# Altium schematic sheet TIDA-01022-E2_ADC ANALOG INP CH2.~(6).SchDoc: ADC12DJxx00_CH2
size 431 x 279 mm; Date: Not shown in title block; ApprovedBy: Not shown in title block; CheckedBy: Not shown in title block; Author: Not shown in title block; CompanyName: Not shown in title block; DrawnBy: Avinash N; Engineer: Not shown in title block; Organization: Not shown in title block; Address1: Not shown in title block; Address2: Not shown in title block; Address3: Not shown in title block; Address4: Not shown in title block; DocumentNumber: 1; Revision: Use project parameter SCH_Rev; SheetNumber: 3; SheetTotal: 26; PageSetup: Record=PageOptions¦CenterHorizontal=True¦CenterVertical=True¦PrintScale=1.00¦XCorrection=1.00¦YCorrection=1.00¦PrintKind=0¦BorderSize=5000000¦LeftOffset=0¦BottomOffset=0¦Orientation=2¦PaperLength=1000¦PaperWidth=1000¦Scale=100¦PaperSource=15¦PrintQuality=600¦MediaType=1¦DitherType=10¦PaperKind=Letter¦PrintScaleMode=1
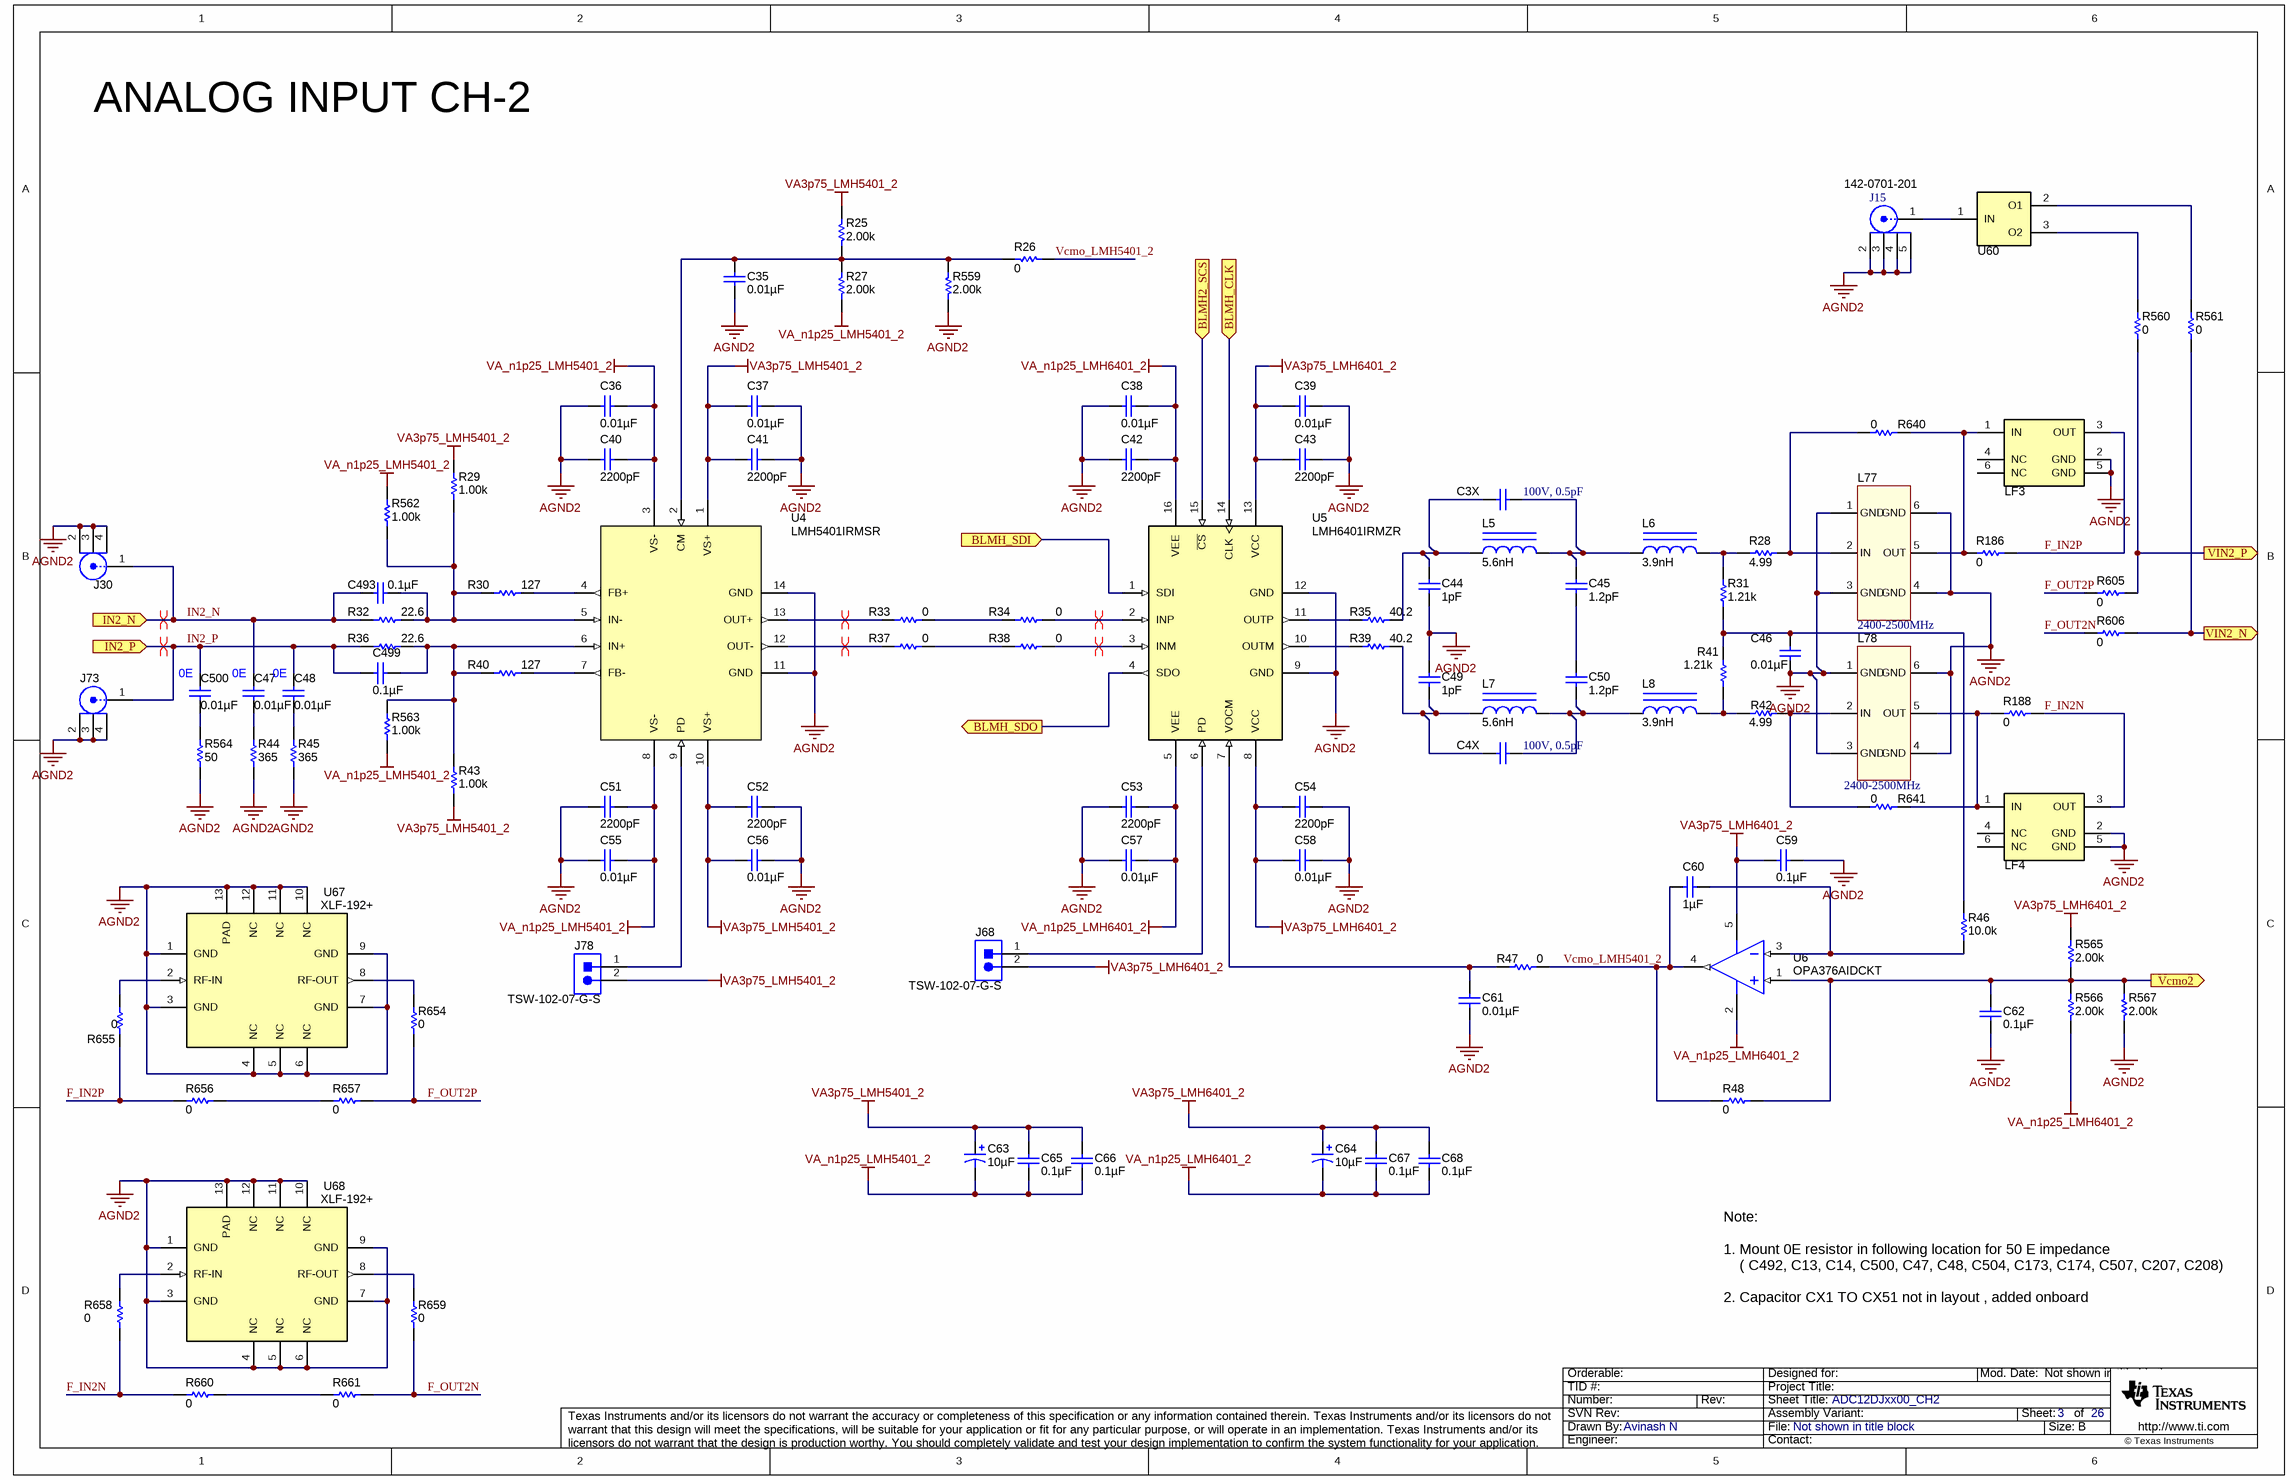
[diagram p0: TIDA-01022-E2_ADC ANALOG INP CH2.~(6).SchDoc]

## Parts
C3X  100V, 0.5pF  [0603_1.6x0.8x0.8mm_Reflow Soldering]
C4X  100V, 0.5pF  [0603_1.6x0.8x0.8mm_Reflow Soldering]
C35  ValueDisplayed: 0.01µF  [0402]  (hidden comment: GRM155R71E103KA01D)
C36  ValueDisplayed: 0.01µF  [0306]  (hidden comment: LLL185R71E103MA01L)
C37  ValueDisplayed: 0.01µF  [0306]  (hidden comment: LLL185R71E103MA01L)
C38  ValueDisplayed: 0.01µF  [0306]  (hidden comment: LLL185R71E103MA01L)
C39  ValueDisplayed: 0.01µF  [0306]  (hidden comment: LLL185R71E103MA01L)
C40  ValueDisplayed: 2200pF  [0306]  (hidden comment: LLL185R71H222MA01L)
C41  ValueDisplayed: 2200pF  [0306]  (hidden comment: LLL185R71H222MA01L)
C42  ValueDisplayed: 2200pF  [0306]  (hidden comment: LLL185R71H222MA01L)
C43  ValueDisplayed: 2200pF  [0306]  (hidden comment: LLL185R71H222MA01L)
C44  ValueDisplayed: 1pF  [0402]  (hidden comment: GRM1555C1H1R0CA01D)
C45  ValueDisplayed: 1.2pF  [0402]  (hidden comment: GRM1555C1H1R2BA01D)
C46  ValueDisplayed: 0.01µF  [0402]  (hidden comment: GRM155R71E103KA01D)
C47  ValueDisplayed: 0.01µF  [0402]  (hidden comment: GRM155R71E103KA01D)
C48  ValueDisplayed: 0.01µF  [0402]  (hidden comment: GRM155R71E103KA01D)
C49  ValueDisplayed: 1pF  [0402]  (hidden comment: GRM1555C1H1R0CA01D)
C50  ValueDisplayed: 1.2pF  [0402]  (hidden comment: GRM1555C1H1R2BA01D)
C51  ValueDisplayed: 2200pF  [0306]  (hidden comment: LLL185R71H222MA01L)
C52  ValueDisplayed: 2200pF  [0306]  (hidden comment: LLL185R71H222MA01L)
C53  ValueDisplayed: 2200pF  [0306]  (hidden comment: LLL185R71H222MA01L)
C54  ValueDisplayed: 2200pF  [0306]  (hidden comment: LLL185R71H222MA01L)
C55  ValueDisplayed: 0.01µF  [0306]  (hidden comment: LLL185R71E103MA01L)
C56  ValueDisplayed: 0.01µF  [0306]  (hidden comment: LLL185R71E103MA01L)
C57  ValueDisplayed: 0.01µF  [0306]  (hidden comment: LLL185R71E103MA01L)
C58  ValueDisplayed: 0.01µF  [0306]  (hidden comment: LLL185R71E103MA01L)
C59  ValueDisplayed: 0.1µF  [0402]  (hidden comment: C1005X5R1A104K050BA)
C60  ValueDisplayed: 1µF  [0603]  (hidden comment: C1608X5R1A105K080AC)
C61  ValueDisplayed: 0.01µF  [0402]  (hidden comment: GRM155R71E103KA01D)
C62  ValueDisplayed: 0.1µF  [0402]  (hidden comment: C1005X5R1A104K050BA)
C63  ValueDisplayed: 10µF  [3216-18]  (hidden comment: TPSA106K010R0900)
C64  ValueDisplayed: 10µF  [3216-18]  (hidden comment: TPSA106K010R0900)
C65  ValueDisplayed: 0.1µF  [0402]  (hidden comment: C1005X5R1A104K050BA)
C66  ValueDisplayed: 0.1µF  [0402]  (hidden comment: C1005X5R1A104K050BA)
C67  ValueDisplayed: 0.1µF  [0402]  (hidden comment: C1005X5R1A104K050BA)
C68  ValueDisplayed: 0.1µF  [0402]  (hidden comment: C1005X5R1A104K050BA)
C493  ValueDisplayed: 0.1µF  [0402]  (hidden comment: GRM155R71C104JA88D)
C499  ValueDisplayed: 0.1µF  [0402]  (hidden comment: GRM155R71C104JA88D)
C500  ValueDisplayed: 0.01µF  [0402]  (hidden comment: GRM155R71E103KA01D)
J15  142-0701-201  [Johnson_142-0701-20x]
J30  142-0771-831  [Johnson_142-0771-831]  (value not drawn)
J68  TSW-102-07-G-S  [TSW-102-07-G-S]
J73  142-0771-831  [Johnson_142-0771-831]  (value not drawn)
J78  TSW-102-07-G-S  [TSW-102-07-G-S]
L5  ValueDisplayed: 5.6nH  [LQW18A]  (hidden comment: LQW18AN5N6D10D)
L6  ValueDisplayed: 3.9nH  [0603HC]  (hidden comment: 0603HC-3N9XJLU)
L7  ValueDisplayed: 5.6nH  [LQW18A]  (hidden comment: LQW18AN5N6D10D)
L8  ValueDisplayed: 3.9nH  [0603HC]  (hidden comment: 0603HC-3N9XJLU)
L77  value 2400-2500MHz  [WE-LPF_0603]  (hidden comment: WE-LPF, 748112024)
L78  value 2400-2500MHz  [WE-LPF_0603]  (hidden comment: WE-LPF, 748112024)
LF3  LFL182G45TC3B746  [FIL_LFL18_TC1]  (value not drawn)
LF4  LFL182G45TC3B746  [FIL_LFL18_TC1]  (value not drawn)
R25  ValueDisplayed: 2.00k  [0402]  (hidden comment: CRCW04022K00FKED)
R26  ValueDisplayed: 0  [0402]  (hidden comment: CRCW04020000Z0ED)
R27  ValueDisplayed: 2.00k  [0402]  (hidden comment: CRCW04022K00FKED)
R28  ValueDisplayed: 4.99  [0402]  (hidden comment: CRCW04024R99FKED)
R29  ValueDisplayed: 1.00k  [0402]  (hidden comment: ERJ-2RKF1001X)
R30  ValueDisplayed: 127  [0402]  (hidden comment: CRCW0402127RFKED)
R31  ValueDisplayed: 1.21k  [0402]  (hidden comment: CRCW04021K21FKED)
R32  ValueDisplayed: 22.6  [0402]  (hidden comment: CRCW040222R6FKED)
R33  ValueDisplayed: 0  [0402]  (hidden comment: CRCW04020000Z0ED)
R34  ValueDisplayed: 0  [0402]  (hidden comment: CRCW04020000Z0ED)
R35  ValueDisplayed: 40.2  [0402]  (hidden comment: CRCW040240R2FKED)
R36  ValueDisplayed: 22.6  [0402]  (hidden comment: CRCW040222R6FKED)
R37  ValueDisplayed: 0  [0402]  (hidden comment: CRCW04020000Z0ED)
R38  ValueDisplayed: 0  [0402]  (hidden comment: CRCW04020000Z0ED)
R39  ValueDisplayed: 40.2  [0402]  (hidden comment: CRCW040240R2FKED)
R40  ValueDisplayed: 127  [0402]  (hidden comment: CRCW0402127RFKED)
R41  ValueDisplayed: 1.21k  [0402]  (hidden comment: CRCW04021K21FKED)
R42  ValueDisplayed: 4.99  [0402]  (hidden comment: CRCW04024R99FKED)
R43  ValueDisplayed: 1.00k  [0402]  (hidden comment: ERJ-2RKF1001X)
R44  ValueDisplayed: 365  [0402]  (hidden comment: CRCW0402365RFKED)
R45  ValueDisplayed: 365  [0402]  (hidden comment: CRCW0402365RFKED)
R46  ValueDisplayed: 10.0k  [0402]  (hidden comment: CRCW040210K0FKED)
R47  ValueDisplayed: 0  [0402]  (hidden comment: CRCW04020000Z0ED)
R48  ValueDisplayed: 0  [0402]  (hidden comment: CRCW04020000Z0ED)
R186  ValueDisplayed: 0  [0402_FILTER]  (hidden comment: CRCW04020000Z0ED)
R188  ValueDisplayed: 0  [0402_FILTER]  (hidden comment: CRCW04020000Z0ED)
R559  ValueDisplayed: 2.00k  [0402]  (hidden comment: CRCW04022K00FKED)
R560  ValueDisplayed: 0  [0201_adc]  (hidden comment: CRCW02010000Z0ED)
R561  ValueDisplayed: 0  [0201_adc]  (hidden comment: CRCW02010000Z0ED)
R562  ValueDisplayed: 1.00k  [0402]  (hidden comment: ERJ-2RKF1001X)
R563  ValueDisplayed: 1.00k  [0402]  (hidden comment: ERJ-2RKF1001X)
R564  ValueDisplayed: 50  [0402]  (hidden comment: FC0402E50R0BTBST1)
R565  ValueDisplayed: 2.00k  [0402]  (hidden comment: CRCW04022K00FKED)
R566  ValueDisplayed: 2.00k  [0402]  (hidden comment: CRCW04022K00FKED)
R567  ValueDisplayed: 2.00k  [0402]  (hidden comment: CRCW04022K00FKED)
R605  ValueDisplayed: 0  [0201_adc]  (hidden comment: CRCW02010000Z0ED)
R606  ValueDisplayed: 0  [0201_adc]  (hidden comment: CRCW02010000Z0ED)
R640  ValueDisplayed: 0  [0402_FILTER]  (hidden comment: CRCW04020000Z0ED)
R641  ValueDisplayed: 0  [0402_FILTER]  (hidden comment: CRCW04020000Z0ED)
R654  ValueDisplayed: 0  [0201_adc]  (hidden comment: CRCW02010000Z0ED)
R655  ValueDisplayed: 0  [0201_adc]  (hidden comment: CRCW02010000Z0ED)
R656  ValueDisplayed: 0  [0201_adc]  (hidden comment: CRCW02010000Z0ED)
R657  ValueDisplayed: 0  [0201_adc]  (hidden comment: CRCW02010000Z0ED)
R658  ValueDisplayed: 0  [0201_adc]  (hidden comment: CRCW02010000Z0ED)
R659  ValueDisplayed: 0  [0201_adc]  (hidden comment: CRCW02010000Z0ED)
R660  ValueDisplayed: 0  [0201_adc]  (hidden comment: CRCW02010000Z0ED)
R661  ValueDisplayed: 0  [0201_adc]  (hidden comment: CRCW02010000Z0ED)
U4  LMH5401IRMSR  [RMS0014A]
U5  LMH6401IRMZR  [RMZ0016A]
U6  OPA376AIDCKT  [DCK0005A_N]
U60  BAL-0006SMG  [Marki_BAL-0006SMG]  (value not drawn)
U67  XLF-192+  [DQ1225]
U68  XLF-192+  [DQ1225]

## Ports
BLMH2_SCS (in), BLMH_CLK (in), BLMH_SDI (in), BLMH_SDO (out), IN2_N (in), IN2_P (in), Vcmo2 (out), VIN2_N (out), VIN2_P (out)

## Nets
AGND2: C35.2 C36.1 C37.1 C38.1 C39.1 C40.2 C41.2 C42.2 C43.2 C44.2 C46.2 C49.2 C51.2 C52.2 C53.2 C54.2 C55.1 C56.1 C57.1 C58.1 C59.1 C61.2 C62.2 J15.2 J15.3 J15.4 J15.5 J30.2 J30.3 J30.4 J73.2 J73.3 J73.4 L77.1(GND) L77.3(GND) L77.4(GND) L77.6(GND) L78.1(GND) L78.3(GND) L78.4(GND) L78.6(GND) LF3.2(GND) LF3.5(GND) LF4.2(GND) LF4.5(GND) R44.1 R45.1 R559.1 R564.1 R567.1 U4.11(GND) U4.14(GND) U5.9(GND) U5.12(GND) U67.1(GND) U67.3(GND) U67.4(NC) U67.5(NC) U67.6(NC) U67.7(GND) U67.9(GND) U67.10(NC) U67.11(NC) U67.12(NC) U67.13(PAD) U68.1(GND) U68.3(GND) U68.4(NC) U68.5(NC) U68.6(NC) U68.7(GND) U68.9(GND) U68.10(NC) U68.11(NC) U68.12(NC) U68.13(PAD)
VA3p75_LMH5401_2: C37.2 C41.1 C52.1 C56.2 C63.1(+) C65.1 C66.1 J78.2 R25.2 R29.2 R43.1 U4.1(VS+) U4.10(VS+)
VA3p75_LMH6401_2: C39.2 C43.1 C54.1 C58.2 C59.2 C64.1(+) C67.1 C68.1 J68.2 R565.2 U5.8(VCC) U5.13(VCC) U6.5(V+)
VA_n1p25_LMH5401_2: C36.2 C40.1 C51.1 C55.2 C63.2(-) C65.2 C66.2 R27.1 R562.2 R563.2 U4.3(VS-) U4.8(VS-)
VA_n1p25_LMH6401_2: C38.2 C42.1 C53.1 C57.2 C64.2(-) C67.2 C68.2 R566.1 U5.5(VEE) U5.16(VEE) U6.2(V-)
BLMH2_SCS: U5.15(~{CS}) ; port BLMH2_SCS
BLMH_CLK: U5.14(CLK) ; port BLMH_CLK
BLMH_SDI: U5.1(SDI) ; port BLMH_SDI
BLMH_SDO: U5.4(SDO) ; port BLMH_SDO
F_IN2N: LF4.3(OUT) R188.2 R658.1 R660.1
F_IN2P: LF3.3(OUT) R186.2 R655.1 R656.1
F_OUT2N: R606.1 R659.1 R661.2
F_OUT2P: R605.1 R654.1 R657.2
IN2_N: C47.1 C493.2 J30.1 R32.1 ; port IN2_N
IN2_P: C48.1 C499.1 C500.1 J73.1 R36.1 ; port IN2_P
Vcmo2: C62.1 R48.1 R565.1 R566.2 R567.2 U6.1(IN+) ; port Vcmo2
Vcmo_LMH5401_2: C60.1 R26.2 R47.1 R48.2 U6.4(OUT)
VIN2_N: R561.2 R606.2 ; port VIN2_N
VIN2_P: R560.2 R605.2 ; port VIN2_P
NetC3X_1: C3X.1 C44.1 L5.1 R35.1
NetC3X_2: C3X.2 C45.1 L5.2 L6.1
NetC4X_1: C4X.1 C49.1 L7.1 R39.1
NetC4X_2: C4X.2 C50.1 L7.2 L8.1
NetC35_1: C35.1 R25.1 R26.1 R27.2 R559.2 U4.2(CM)
NetC45_2: C45.2 C50.2
NetC46_1: C46.1 R31.1 R41.1 R46.2
NetC47_2: C47.2 R44.2
NetC48_2: C48.2 R45.2
NetC60_2: C60.2 R46.1 U6.3(IN-)
NetC61_1: C61.1 R47.2 U5.7(VOCM)
NetC493_1: C493.1 R29.1 R30.1 R32.2 R562.1 U4.5(IN-)
NetC499_2: C499.2 R36.2 R40.1 R43.2 R563.1 U4.6(IN+)
NetC500_2: C500.2 R564.2
NetJ15_1: J15.1 U60.1(IN)
NetJ68_1: J68.1 U5.6(PD)
NetJ78_1: J78.1 U4.9(PD)
NetL6_2: L6.2 R28.1 R31.2
NetL8_2: L8.2 R41.2 R42.1
NetL77_2: L77.2(IN) R28.2 R640.1
NetL77_5: L77.5(OUT) LF3.1(IN) R186.1 R640.2
NetL78_2: L78.2(IN) R42.2 R641.1
NetL78_5: L78.5(OUT) LF4.1(IN) R188.1 R641.2
NetR30_2: R30.2 U4.4(FB+)
NetR33_1: R33.1 U4.13(OUT+)
NetR33_2: R33.2 R34.2
NetR34_1: R34.1 U5.2(INP)
NetR35_2: R35.2 U5.11(OUTP)
NetR37_1: R37.1 U4.12(OUT-)
NetR37_2: R37.2 R38.2
NetR38_1: R38.1 U5.3(INM)
NetR39_2: R39.2 U5.10(OUTM)
NetR40_2: R40.2 U4.7(FB-)
NetR560_1: R560.1 U60.3(O2)
NetR561_1: R561.1 U60.2(O1)
NetR654_2: R654.2 U67.8(RF-OUT)
NetR655_2: R655.2 U67.2(RF-IN)
NetR656_2: R656.2 R657.1
NetR658_2: R658.2 U68.2(RF-IN)
NetR659_2: R659.2 U68.8(RF-OUT)
NetR660_2: R660.2 R661.1

Not connected (* = marked no-connect by the designer): LF3 4(NC) 6(NC); LF4 4(NC) 6(NC)

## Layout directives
differential pair: IN2_N, IN2_P, NetR33_1, NetR34_1, NetR37_1, NetR38_1

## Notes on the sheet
- ANALOG INPUT CH-2
- (near C500) 0E
- (near C47) 0E
- (near C48) 0E
- Note:
  1. Mount 0E resistor in following location for 50 E impedance
  ( C492, C13, C14, C500, C47, C48, C504, C173, C174, C507, C207, C208)
  2. Capacitor CX1 TO CX51 not in layout , added onboard

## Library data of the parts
C3X C4X = 885012006086: WCAP-CSGP Ceramic Capacitors, 0603, NP0, 100V, 0.5pF; Rated Voltage: 100V DC
C35 C46-C48 C61 C500 = GRM155R71E103KA01D: CAP, CERM, 0.01 µF, 25 V, +/- 10%, X7R, 0402; Manufacturer: MuRata; Polarized: N; CompType: Capacitor; Value: 0.01uF; U/M: EA; Cap_F: 0.00000001; Tolerance_%: 10; Value1: Unknown; VDC_V: 25; Value2: 25V; TaMin_C: -55; TaMax_C: 125; SizeArea_mm2: 0.5; SizeAreaWB_mm2: 3; SizeX_mm: 1; SizeZ_mm: 0.6; AEC Category: Q200
C36-C39 C55-C58 = LLL185R71E103MA01L: CAP, CERM, 0.01 µF, 25 V, +/- 20%, X7R, 0306; Manufacturer: MuRata; Polarized: N; CompType: Capacitor; Value: 0.01uF; U/M: EA; Cap_F: 0.00000001; Tolerance_%: 20; Value1: Unknown; VDC_V: 25; Value2: 25V; TaMin_C: -55; TaMax_C: 125; SizeArea_mm2: 1.28; SizeAreaWB_mm2: 4.68; SizeX_mm: 0.8; SizeY_mm: 1.6; SizeZ_mm: 0.6; AEC Category: Q200
C40-C43 C51-C54 = LLL185R71H222MA01L: CAP, CERM, 2200 pF, 50 V, +/- 20%, X7R, 0306; Manufacturer: MuRata; Polarized: N; CompType: Capacitor; Value: 2200pF; U/M: EA; Cap_F: 0.0000000022; Tolerance_%: 20; Value1: Unknown; VDC_V: 50; Value2: 50V; TaMin_C: -55; TaMax_C: 125; SizeArea_mm2: 1.28; SizeAreaWB_mm2: 4.68; SizeX_mm: 0.8; SizeY_mm: 1.6; SizeZ_mm: 0.6; AEC Category: Q200
C44 C49 = GRM1555C1H1R0CA01D: CAP, CERM, 1 pF, 50 V, +/- 5%, C0G/NP0, 0402; Manufacturer: MuRata; Polarized: N; CompType: Capacitor; Value: 1pF; U/M: EA; Cap_F: 0.000000000001; Tolerance_%: 5; Value1: Unknown; VDC_V: 50; Value2: 50V; TaMin_C: -55; TaMax_C: 125; SizeArea_mm2: 0.5; SizeAreaWB_mm2: 3; SizeX_mm: 1; SizeZ_mm: 0.6; AEC Category: Q200
C45 C50 = GRM1555C1H1R2BA01D: CAP, CERM, 1.2 pF, 50 V, +/- 8.3%, C0G/NP0, 0402; Manufacturer: MuRata; Polarized: N; CompType: Capacitor; Value: 1.2pF; U/M: EA; Cap_F: 0.0000000000012; Tolerance_%: 8.3; Value1: Unknown; VDC_V: 50; Value2: 50V; TaMin_C: -55; TaMax_C: 125; SizeArea_mm2: 0.5; SizeAreaWB_mm2: 3; SizeX_mm: 1; SizeZ_mm: 0.6; AEC Category: Q200
C59 C62 C65-C68 = C1005X5R1A104K050BA: CAP, CERM, 0.1 µF, 10 V, +/- 10%, X5R, 0402; Manufacturer: TDK; Polarized: N; CompType: Capacitor; Value: 0.1uF; U/M: EA; Cap_F: 0.0000001; Tolerance_%: 10; Value1: Unknown; Value2: 10V; TaMin_C: -55; TaMax_C: 85; SizeArea_mm2: 0.5; SizeAreaWB_mm2: 3; SizeX_mm: 1; SizeZ_mm: 0.6; AEC Category: Q200
C60 = C1608X5R1A105K080AC: CAP, CERM, 1 µF, 10 V, +/- 10%, X5R, 0603; Manufacturer: TDK; Polarized: N; CompType: Capacitor; Value: 1uF; U/M: EA; Cap_F: 0.000001; Tolerance_%: 10; Value1: Unknown; Value2: 10V; TaMin_C: -55; TaMax_C: 85; SizeArea_mm2: 1.28; SizeAreaWB_mm2: 4.68; SizeX_mm: 1.6; SizeY_mm: 0.8; SizeZ_mm: 1; AEC Category: Q200
C63 C64 = TPSA106K010R0900: CAP, TA, 10 µF, 10 V, +/- 10%, 0.9 ohm, SMD; Manufacturer: AVX; Polarized: Y; CompType: Capacitor; Value: 10uF; U/M: EA; Cap_F: 0.00001; Tolerance_%: 10; Value1: 0.9 ohm; Value2: 10V; ESR_ohm: 0.9; IRMS_A: 0.26; TaMin_C: -55; TaMax_C: 125; Cap_Case: A; SizeAreaWB_mm2: 10.92; SizeArea_mm2: 5.12; SizeX_mm: 3.2; SizeY_mm: 1.6; SizeZ_mm: 1.8; AEC Category: Q200
C493 C499 = GRM155R71C104JA88D: CAP, CERM, 0.1 µF, 16 V, +/- 5%, X7R, 0402; Manufacturer: MuRata; Polarized: N; CompType: Capacitor; Value: 0.1uF; U/M: EA; Cap_F: 0.0000001; Tolerance_%: 5; Value1: Unknown; VDC_V: 16; Value2: 16V; TaMin_C: -55; TaMax_C: 125; SizeArea_mm2: 0.5; SizeAreaWB_mm2: 3; SizeX_mm: 1; SizeZ_mm: 0.6; AEC Category: Q200
J15 = 142-0701-201: Connector, TH, SMA; Manufacturer: Emerson Network Power; SymbolCreator: X0208326
J30 J73 = 142-0771-831: JACK, SMA, 50 Ohm, Gold, Edge Mount; Manufacturer: Johnson; SymbolCreator: Altium; Gender: Female; Voltage_V: 170
J68 J78 = TSW-102-07-G-S: Header, 100mil, 2x1, Gold, TH; Manufacturer: Samtec; SymbolCreator: a0412235; Pitch_mm: 2.54; Gender: Male; Shrouded: N; Row_Count: 1; Current_A: 6.3; Voltage_V: 550; Cert_CSA: Y
L5 L7 = LQW18AN5N6D10D: Inductor, Wirewound, 5.6 nH, 0.9 A, 0.045 ohm, SMD; Manufacturer: MuRata; Value: 5.6nH; Ind_H: 5.6E-9; Imax_A: 0.9; Irms: 0.9A @ C rise; DCR_ohm: 0.045; Value2: 0.9A; SizeAreaWB_mm2: 4.68; SizeArea_mm2: 1.28; SizeX_mm: 1.6; SizeY_mm: 0.8; SizeZ_mm: 1; AEC Category: Q200; AEC Qualified: N
L6 L8 = 0603HC-3N9XJLU: Inductor, Wirewound, Ceramic, 3.9 nH, 2.2 A, 0.054 ohm, SMD; Manufacturer: Coilcraft; Value: 3.9nH; Ind_H: 3.9E-9; Imax_A: 2.2; Irms: 2.4A @ 20C rise; DCR_ohm: 0.054; Value2: 2.2A; SizeAreaWB_mm2: 5.936; SizeArea_mm2: 2.016; SizeX_mm: 1.8; SizeY_mm: 1.12; SizeZ_mm: 1.02; AEC Category: Q200
L77 L78 = WE-LPF, 748112024: WE-LPF Multilayer Chip Low-Pass Filter, size 0603, 2400-2500MHz
LF3 LF4 = LFL182G45TC3B746: Filter for Communication Equipment, SMD; Manufacturer: MuRata; SymbolCreator: Altium; SizeAreaWB_mm2: 4.68; SizeArea_mm2: 1.28; SizeX_mm: 1.6; SizeY_mm: 0.8; SizeZ_mm: 0.7
R25 R27 R559 R565-R567 = CRCW04022K00FKED: RES, 2.00 k, 1%, 0.063 W, 0402; Manufacturer: Vishay-Dale; CompType: Resistor; Value: 2.00k; Res_ohm: 2000; Value_Code: 2k00; Tolerance_%: 1; Power_W: 0.063; Value2: 0.063W; VDC_V: 50; TempCo: 100 ppm/C; SizeArea_mm2: 0.5; SizeZ_mm: 0.6; EIA_Code: E96; U/M: EA; AEC Category: Q200
R26 R33 R34 R37 R38 R47 R48 R186 R188 R640 R641 = CRCW04020000Z0ED: RES, 0, 5%, 0.063 W, 0402; Manufacturer: Vishay-Dale; CompType: Resistor; Value: 0; Value_Code: 0000; Tolerance_%: 5; Power_W: 0.063; Value2: 0.063W; VDC_V: 50; TempCo: 200 ppm/C; SizeArea_mm2: 0.5; SizeX_mm: 1; SizeZ_mm: 0.6; EIA_Code: E24; U/M: EA; AEC Category: Q200
R28 R42 = CRCW04024R99FKED: RES, 4.99, 1%, 0.063 W, 0402; Manufacturer: Vishay-Dale; CompType: Resistor; Value: 4.99; Value_Code: 4R99; Tolerance_%: 1; Power_W: 0.063; Value2: 0.063W; VDC_V: 50; TempCo: 100 ppm/C; SizeArea_mm2: 0.5; SizeZ_mm: 0.6; EIA_Code: E96; U/M: EA; AEC Category: Q200
R29 R43 R562 R563 = ERJ-2RKF1001X: RES, 1.00 k, 1%, 0.1 W, 0402; Manufacturer: Panasonic; CompType: Resistor; Value: 1.00k; Res_ohm: 1000; Value_Code: 1k00; Tolerance_%: 1; Power_W: 0.1; Value2: 0.1W; VDC_V: 50; TempCo: 100 ppm/C; SizeArea_mm2: 0.5; SizeZ_mm: 0.6; EIA_Code: E96; U/M: EA; AEC Category: Q200
R30 R40 = CRCW0402127RFKED: RES, 127, 1%, 0.063 W, 0402; Manufacturer: Vishay-Dale; CompType: Resistor; Value: 127; Value_Code: 127R; Tolerance_%: 1; Power_W: 0.063; Value2: 0.063W; VDC_V: 50; TempCo: 100 ppm/C; SizeArea_mm2: 0.5; SizeZ_mm: 0.6; EIA_Code: E96; U/M: EA; AEC Category: Q200
R31 R41 = CRCW04021K21FKED: RES, 1.21 k, 1%, 0.063 W, 0402; Manufacturer: Vishay-Dale; CompType: Resistor; Value: 1.21k; Res_ohm: 1210; Value_Code: 1k21; Tolerance_%: 1; Power_W: 0.063; Value2: 0.063W; VDC_V: 50; TempCo: 100 ppm/C; SizeArea_mm2: 0.5; SizeZ_mm: 0.6; EIA_Code: E96; U/M: EA; AEC Category: Q200
R32 R36 = CRCW040222R6FKED: RES, 22.6, 1%, 0.063 W, 0402; Manufacturer: Vishay-Dale; CompType: Resistor; Value: 22.6; Value_Code: 22R6; Tolerance_%: 1; Power_W: 0.063; Value2: 0.063W; VDC_V: 50; TempCo: 100 ppm/C; SizeArea_mm2: 0.5; SizeZ_mm: 0.6; EIA_Code: E96; U/M: EA; AEC Category: Q200
R35 R39 = CRCW040240R2FKED: RES, 40.2, 1%, 0.063 W, 0402; Manufacturer: Vishay-Dale; CompType: Resistor; Value: 40.2; Value_Code: 40R2; Tolerance_%: 1; Power_W: 0.063; Value2: 0.063W; VDC_V: 50; TempCo: 100 ppm/C; SizeArea_mm2: 0.5; SizeZ_mm: 0.6; EIA_Code: E96; U/M: EA; AEC Category: Q200
R44 R45 = CRCW0402365RFKED: RES, 365, 1%, 0.063 W, 0402; Manufacturer: Vishay-Dale; CompType: Resistor; Value: 365; Value_Code: 365R; Tolerance_%: 1; Power_W: 0.063; Value2: 0.063W; VDC_V: 50; TempCo: 100 ppm/C; SizeArea_mm2: 0.5; SizeZ_mm: 0.6; EIA_Code: E96; U/M: EA; AEC Category: Q200
R46 = CRCW040210K0FKED: RES, 10.0 k, 1%, 0.063 W, 0402; Manufacturer: Vishay-Dale; CompType: Resistor; Value: 10.0k; Res_ohm: 10000; Value_Code: 10k0; Tolerance_%: 1; Power_W: 0.063; Value2: 0.063W; VDC_V: 50; TempCo: 100 ppm/C; SizeArea_mm2: 0.5; SizeZ_mm: 0.6; EIA_Code: E96; U/M: EA; AEC Category: Q200
R560 R561 R605 R606 R654-R661 = CRCW02010000Z0ED: RES, 0, 5%, 0.05 W, 0201; Manufacturer: Vishay-Dale; CompType: Resistor; Value: 0; Value_Code: 0000; Tolerance_%: 5; Power_W: 0.05; Value2: 0.05W; TempCo: ppm/C; SizeArea_mm2: 0.18; SizeX_mm: 0.6; SizeY_mm: 0.3; SizeZ_mm: 0.26; EIA_Code: E24; U/M: EA; AEC Category: Q200; AEC Qualified: N
R564 = FC0402E50R0BTBST1: RES, 50, 0.1%, 0.5 W, 0402; Manufacturer: Vishay Thin Film; CompType: Resistor; Value: 50; Value_Code: 50R0; Tolerance_%: 0.1; Power_W: 0.5; Value2: 0.5W; TempCo: 0.1 ppm/C; SizeX_mm: 1; SizeZ_mm: 0.6; U/M: EA; AEC Category: Q200; AEC Qualified: N
U4 = LMH5401IRMSR: 8GHz Ultra Wideband Fully Differential Amplifier, RMS0014A (UQFN-14); Alternate PartNumber: LMH5401IRMST; Manufacturer: Texas Instruments; SymbolCreator: Altium; SizeArea_mm2: 6.25; SizeAreaWB_mm2: 12.25; SizeX_mm: 2.5; SizeZ_mm: 0.6; CompType: IC; U/M: EA
U5 = LMH6401IRMZR: 4.5 GHz Ultra Wideband Digital Variable Gain Amplifier, RMZ0016A (UQFN-HR-16); Alternate PartNumber: LMH6401IRMZT; Manufacturer: Texas Instruments; SymbolCreator: Altium; SizeArea_mm2: 9; SizeAreaWB_mm2: 16; SizeX_mm: 3; SizeZ_mm: 0.65; CompType: IC; U/M: EA
U6 = OPA376AIDCKT: Precision, Low Noise, Low Iq Operational Amplifier, 2.2 to 5.5 V, -40 to 125 degC, 5-pin SOT23 (DCK0005A), Green (RoHS & no Sb/Br); Manufacturer: Texas Instruments; Alternate PartNumber: Equivalent; CMRR(Min)(dB): 76; IIB(Max)(pA): 10; Iq per channel(Max)(mA): 0.95; Number of Channels: 1; Offset Drift(Typ)(uV/C): 0.32; Slew Rate(Typ)(V/us): 2; Sub Family: Low Input Bias Current Amp (<=10pA), Low Noise Amp (<=10nV/rtHz), Low Offset Voltage Amplifier (<=500uV), Low Supply Voltage Amplifier (<=2.7V), Precision Amplifier; Total Supply Voltage(Max)(+5V is 5, +/-5V is 10): 5.5; Total Supply Voltage(Min)(+5V is 5, +/-5V is 10): 2.2; Vio (25C)(Max)(mV): 0.025; Vn at 1kHz(Typ)(nV/rtHz): 7.5
U60 = BAL-0006SMG: Broadband Balun, 500 kHz to 6 GHz; Manufacturer: Marki Microwave; SymbolCreator: Altium; SizeAreaWB_mm2: 102.6169; SizeArea_mm2: 66.0969; SizeX_mm: 8.13; SizeZ_mm: 3.94
U67 U68 = CMP-0077784-1: Reflectionless Low Pass Filter, SMD; Manufacturer: Minicircuits; SizeArea_mm2: 9; SizeAreaWB_mm2: 16; SizeY_mm: 3; SizeZ_mm: 0.89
